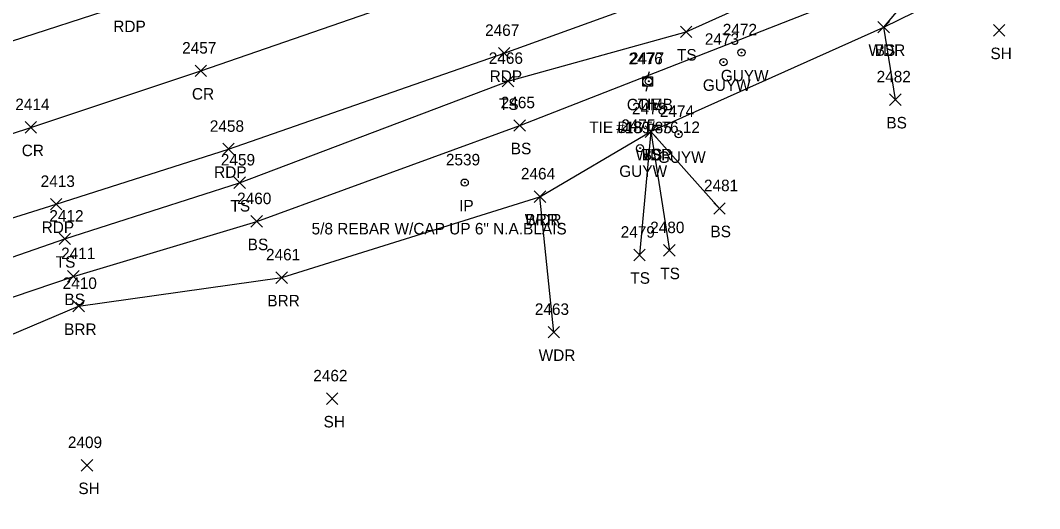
# Model space of a CAD drawing. Extents: x 1699408 to 1700423, y 840176 to 841410.
# Drawn here: x 1700025.1 to 1700202.3, y 840316.1 to 840401 of the extents above; entities that cross this region are included whole.
import ezdxf

# ---------------------------------------------------------------- set-up
doc = ezdxf.new("R2010")
doc.units = 0
for name, color, linetype in [('C_A', 7, 'Continuous'), ('C_C', 7, 'Continuous'), ('C_I', 7, 'Continuous'), ('CBP', 7, 'Continuous'), ('L_A', 7, 'Continuous'), ('L_I', 7, 'Continuous'), ('L_TIC', 7, 'Continuous'), ('LABL', 7, 'Continuous'), ('LAWA', 7, 'Continuous'), ('LELB', 7, 'Continuous'), ('M_A', 7, 'Continuous'), ('M_C', 7, 'Continuous'), ('M_I', 7, 'Continuous'), ('MPIR', 7, 'Continuous'), ('P_A', 7, 'Continuous'), ('P_I', 7, 'Continuous'), ('P_TIC', 7, 'Continuous'), ('PET', 7, 'Continuous'), ('PRC', 7, 'Continuous'), ('U_A', 7, 'Continuous'), ('U_C', 7, 'Continuous'), ('U_I', 7, 'Continuous'), ('UP', 7, 'Continuous'), ('UPGW', 7, 'Continuous')]:
    doc.layers.add(name, color=color, linetype=linetype)

msp = doc.modelspace()

# ---------------------------------------------------------------- linework, layer by layer
at = {"layer": 'CBP'}
for radius in [0.625, 0.0833]:
    msp.add_circle((1700134.38, 840390.4), radius, dxfattribs=at)
at = {"layer": 'L_TIC'}
for points in [[(1700139.91, 840398), (1700141.91, 840400)], [(1700141.91, 840398), (1700139.91, 840400)], [(1700174.24, 840398.81), (1700176.24, 840400.81)], [(1700176.24, 840398.81), (1700174.24, 840400.81)], [(1700174.24, 840398.81), (1700176.24, 840400.81)], [(1700176.24, 840398.81), (1700174.24, 840400.81)], [(1700194.31, 840398.24), (1700196.31, 840400.24)], [(1700196.31, 840398.24), (1700194.31, 840400.24)], [(1700108.93, 840389.42), (1700110.93, 840391.42)], [(1700110.93, 840389.42), (1700108.93, 840391.42)], [(1700176.27, 840386.2), (1700178.27, 840388.2)], [(1700178.27, 840386.2), (1700176.27, 840388.2)], [(1700110.96, 840381.71), (1700112.96, 840383.71)], [(1700112.96, 840381.71), (1700110.96, 840383.71)], [(1700133.74, 840380.65), (1700135.74, 840382.65)], [(1700135.74, 840380.65), (1700133.74, 840382.65)], [(1700133.74, 840380.65), (1700135.74, 840382.65)], [(1700135.74, 840380.65), (1700133.74, 840382.65)], [(1700133.74, 840380.65), (1700135.74, 840382.65)], [(1700135.74, 840380.65), (1700133.74, 840382.65)], [(1700133.74, 840380.65), (1700135.74, 840382.65)], [(1700135.74, 840380.65), (1700133.74, 840382.65)], [(1700062.25, 840371.76), (1700064.25, 840373.76)], [(1700064.25, 840371.76), (1700062.25, 840373.76)], [(1700114.47, 840369.34), (1700116.47, 840371.34)], [(1700116.47, 840369.34), (1700114.47, 840371.34)], [(1700114.47, 840369.34), (1700116.47, 840371.34)], [(1700116.47, 840369.34), (1700114.47, 840371.34)], [(1700145.68, 840367.29), (1700147.68, 840369.29)], [(1700147.68, 840367.29), (1700145.68, 840369.29)], [(1700065.22, 840365.04), (1700067.22, 840367.04)], [(1700067.22, 840365.04), (1700065.22, 840367.04)], [(1700031.87, 840362), (1700033.87, 840364)], [(1700033.87, 840362), (1700031.87, 840364)], [(1700131.78, 840359.21), (1700133.78, 840361.21)], [(1700133.78, 840359.21), (1700131.78, 840361.21)], [(1700136.98, 840360), (1700138.98, 840362)], [(1700138.98, 840360), (1700136.98, 840362)], [(1700033.35, 840355.49), (1700035.35, 840357.49)], [(1700035.35, 840355.49), (1700033.35, 840357.49)], [(1700069.58, 840355.27), (1700071.58, 840357.27)], [(1700071.58, 840355.27), (1700069.58, 840357.27)], [(1700034.26, 840350.3), (1700036.26, 840352.3)], [(1700036.26, 840350.3), (1700034.26, 840352.3)], [(1700116.89, 840345.79), (1700118.89, 840347.79)], [(1700118.89, 840345.79), (1700116.89, 840347.79)], [(1700078.36, 840334.24), (1700080.36, 840336.24)], [(1700080.36, 840334.24), (1700078.36, 840336.24)], [(1700035.73, 840322.65), (1700037.73, 840324.65)], [(1700037.73, 840322.65), (1700035.73, 840324.65)]]:
    msp.add_lwpolyline(points, dxfattribs=at)
at = {"layer": 'LABL'}
msp.add_lwpolyline([(1699953.28, 840316.13), (1699979.6, 840328.94), (1700004.87, 840338.43), (1700035.26, 840351.3), (1700070.58, 840356.27), (1700115.47, 840370.34)], dxfattribs=at)
at = {"layer": 'LAWA'}
msp.add_lwpolyline([(1700117.89, 840346.79), (1700115.47, 840370.34), (1700134.74, 840381.65), (1700175.24, 840399.81), (1700196.37, 840410.18), (1700227.82, 840422.6), (1700263.02, 840437.63), (1700310.41, 840452.18), (1700348.89, 840465.62), (1700387.69, 840477.37), (1700417.82, 840485.58)], dxfattribs=at)
at = {"layer": 'LELB'}
for points in [[(1699894.91, 840318.62), (1699909.54, 840320.37), (1699931.73, 840326.89), (1699942.77, 840330.34), (1699953.04, 840332.24), (1699965.49, 840337.33), (1699971.91, 840344.73), (1700003.63, 840352.88), (1700032.87, 840363), (1700063.25, 840372.76), (1700109.93, 840390.42), (1700140.91, 840399), (1700170.04, 840412.16), (1700222.58, 840432.8), (1700261.59, 840445.7), (1700307.68, 840461.11), (1700347.68, 840474.56), (1700384.18, 840486.92), (1700414.06, 840495.99)], [(1699950.19, 840322.46), (1699970.52, 840330.95), (1699975.9, 840338.67), (1700003.21, 840345.94), (1700034.35, 840356.49), (1700066.22, 840366.04), (1700111.96, 840382.71), (1700172.64, 840406.47), (1700188.14, 840417.18), (1700223.53, 840430.55), (1700261.76, 840444.29), (1700308.01, 840458.93), (1700347.92, 840472.31), (1700385.46, 840483.48), (1700416.04, 840491.19)], [(1700177.27, 840387.2), (1700175.24, 840399.81), (1700188.97, 840416.03), (1700224.35, 840428.66), (1700261.3, 840441.34), (1700309.36, 840456.05), (1700348.46, 840469.98), (1700386.66, 840479.73), (1700417.03, 840487.78)], [(1700134.74, 840381.65), (1700132.78, 840360.21)], [(1700134.74, 840381.65), (1700146.68, 840368.29)], [(1700134.74, 840381.65), (1700137.98, 840361)]]:
    msp.add_lwpolyline(points, dxfattribs=at)
at = {"layer": 'MPIR'}
for radius in [0.625, 0.0833]:
    msp.add_circle((1700102.39, 840372.78), radius, dxfattribs=at)
at = {"layer": 'P_TIC'}
for points in [[(1700108.24, 840394.28), (1700110.24, 840396.28)], [(1700110.24, 840394.28), (1700108.24, 840396.28)], [(1700055.52, 840391.21), (1700057.52, 840393.21)], [(1700057.52, 840391.21), (1700055.52, 840393.21)], [(1700025.94, 840381.38), (1700027.94, 840383.38)], [(1700027.94, 840381.38), (1700025.94, 840383.38)], [(1700060.33, 840377.61), (1700062.33, 840379.61)], [(1700062.33, 840377.61), (1700060.33, 840379.61)], [(1700030.35, 840368.03), (1700032.35, 840370.03)], [(1700032.35, 840368.03), (1700030.35, 840370.03)]]:
    msp.add_lwpolyline(points, dxfattribs=at)
at = {"layer": 'PET'}
for points in [[(1700021.62, 840396.71), (1700043.81, 840403.93), (1700089.04, 840420.89), (1700114.15, 840429.08), (1700156, 840442.24), (1700184.2, 840452.68), (1700219.84, 840464.9), (1700253.86, 840476.91), (1700292.78, 840490.43), (1700340.75, 840506.36), (1700375.21, 840518.2), (1700402.6, 840527.14)], [(1700000.7, 840359.42), (1700031.35, 840369.03), (1700061.33, 840378.61), (1700109.24, 840395.28), (1700138.79, 840406.02), (1700172.93, 840418.49), (1700221.46, 840435.72), (1700260.32, 840448.69), (1700306.34, 840464.7), (1700346.69, 840478.05), (1700382.8, 840490.67), (1700413.01, 840500.61)]]:
    msp.add_lwpolyline(points, dxfattribs=at)
at = {"layer": 'PRC'}
msp.add_lwpolyline([(1699996.81, 840372.51), (1700026.94, 840382.38), (1700056.52, 840392.21), (1700105.22, 840409.05), (1700134.27, 840419.13), (1700168.35, 840431.32), (1700216.93, 840448.55), (1700256.68, 840462.13), (1700302.17, 840477.7), (1700342.85, 840491.54), (1700378.3, 840503.62), (1700408.52, 840513.62)], dxfattribs=at)
at = {"layer": 'UP'}
for p, q in [((1700133.36, 840389.52), (1700133.36, 840391.19)), ((1700133.36, 840391.19), (1700135.03, 840391.19)), ((1700134.44, 840392.02), (1700134.19, 840391.19)), ((1700135.03, 840391.19), (1700135.03, 840389.52)), ((1700135.03, 840389.52), (1700133.36, 840389.52)), ((1700133.94, 840388.69), (1700134.19, 840389.52)), ((1700134.19, 840390.35), (1700134.19, 840390.35))]:
    msp.add_line(p, q, dxfattribs=at)
msp.add_circle((1700134.19, 840390.35), 0.833, dxfattribs=at)
at = {"layer": 'UPGW'}
for centre, radius in [((1700150.52, 840395.38), 0.625), ((1700150.52, 840395.38), 0.0833), ((1700147.4, 840393.73), 0.625), ((1700147.4, 840393.73), 0.0833), ((1700139.58, 840381.21), 0.625), ((1700139.58, 840381.21), 0.0833), ((1700132.87, 840378.77), 0.625), ((1700132.87, 840378.77), 0.0833)]:
    msp.add_circle(centre, radius, dxfattribs=at)

# ---------------------------------------------------------------- texts
at = {"layer": 'C_A'}
msp.add_text('TIE', height=2, dxfattribs=at).set_placement((1700132.46, 840385.4))
at = {"layer": 'C_C'}
msp.add_text('TIE DIST=76.12', height=2, dxfattribs=at).set_placement((1700124.04, 840381.4))
at = {"layer": 'C_I'}
msp.add_text('2477', height=2, dxfattribs=at).set_placement((1700131.12, 840393.4))
at = {"layer": 'L_A'}
for s, p in [('WDR', (1700172.6, 840394.81)), ('BS', (1700173.68, 840394.81)), ('TS', (1700139.31, 840394)), ('SH', (1700193.8, 840394.24)), ('TS', (1700108.34, 840385.42)), ('BS', (1700175.71, 840382.2)), ('BS', (1700110.4, 840377.71)), ('WDR', (1700132.1, 840376.65)), ('TS', (1700133.15, 840376.65)), ('TS', (1700133.15, 840376.65)), ('BS', (1700133.18, 840376.65)), ('TS', (1700061.66, 840367.76)), ('WDR', (1700112.83, 840365.34)), ('BRR', (1700112.95, 840365.34)), ('BS', (1700145.12, 840363.29)), ('BS', (1700064.66, 840361.04)), ('TS', (1700031.28, 840358)), ('TS', (1700136.39, 840356)), ('TS', (1700131.19, 840355.21)), ('BS', (1700032.79, 840351.49)), ('BRR', (1700068.07, 840351.27)), ('BRR', (1700032.74, 840346.3)), ('WDR', (1700115.25, 840341.79)), ('SH', (1700077.85, 840330.24)), ('SH', (1700035.22, 840318.65))]:
    msp.add_text(s, height=2, dxfattribs=at).set_placement(p)
at = {"layer": 'L_I'}
for s, p in [('2466', (1700106.57, 840393.42)), ('2482', (1700174.01, 840390.2)), ('2465', (1700108.65, 840385.71)), ('2478', (1700131.48, 840384.65)), ('2478', (1700131.48, 840384.65)), ('2478', (1700131.48, 840384.65)), ('2478', (1700131.48, 840384.65)), ('2459', (1700059.99, 840375.76)), ('2464', (1700112.16, 840373.34)), ('2464', (1700112.16, 840373.34)), ('2481', (1700143.99, 840371.29)), ('2460', (1700062.82, 840369.04)), ('2412', (1700030.17, 840366)), ('2479', (1700129.51, 840363.21)), ('2480', (1700134.64, 840364)), ('2411', (1700032.22, 840359.49)), ('2461', (1700067.84, 840359.27)), ('2410', (1700032.48, 840354.3)), ('2463', (1700114.58, 840349.79)), ('2462', (1700076.06, 840338.24)), ('2409', (1700033.39, 840326.65))]:
    msp.add_text(s, height=2, dxfattribs=at).set_placement(p)
at = {"layer": 'M_A'}
msp.add_text('IP', height=2, dxfattribs=at).set_placement((1700101.43, 840367.78))
at = {"layer": 'M_C'}
msp.add_text('5/8 REBAR W/CAP UP 6" N.A.BLAIS', height=2, dxfattribs=at).set_placement((1700075.77, 840363.78))
at = {"layer": 'M_I'}
msp.add_text('2539', height=2, dxfattribs=at).set_placement((1700099.12, 840375.78))
at = {"layer": 'P_A'}
for s, p in [('RDP', (1700041.29, 840398.93)), ('RDP', (1700041.29, 840398.93)), ('RDP', (1700106.73, 840390.28)), ('CR', (1700054.96, 840387.21)), ('CR', (1700025.37, 840377.38)), ('RDP', (1700058.82, 840373.61)), ('RDP', (1700028.84, 840364.03))]:
    msp.add_text(s, height=2, dxfattribs=at).set_placement(p)
at = {"layer": 'P_I'}
for s, p in [('2467', (1700105.93, 840398.28)), ('2457', (1700053.26, 840395.21)), ('2414', (1700024.25, 840385.38)), ('2458', (1700058.07, 840381.61)), ('2413', (1700028.66, 840372.03))]:
    msp.add_text(s, height=2, dxfattribs=at).set_placement(p)
at = {"layer": 'U_A'}
for s, p in [('GUYW', (1700146.91, 840390.38)), ('GUYW', (1700143.79, 840388.73)), ('COMB', (1700130.58, 840385.35)), ('GUYW', (1700135.97, 840376.21)), ('GUYW', (1700129.26, 840373.77))]:
    msp.add_text(s, height=2, dxfattribs=at).set_placement(p)
at = {"layer": 'U_C'}
msp.add_text('#189/85', height=2, dxfattribs=at).set_placement((1700128.73, 840381.35))
at = {"layer": 'U_I'}
for s, p in [('2472', (1700147.26, 840398.38)), ('2473', (1700144.14, 840396.73)), ('2476', (1700130.88, 840393.35)), ('2474', (1700136.32, 840384.21)), ('2475', (1700129.61, 840381.77))]:
    msp.add_text(s, height=2, dxfattribs=at).set_placement(p)

doc.saveas('drawing.dxf')
